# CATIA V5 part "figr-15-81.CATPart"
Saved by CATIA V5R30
Part number: Part1
Bounding box of the stored display mesh (mm): x -28.659 to 28.659, y -52 to 52, z 0 to 2
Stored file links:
  D:\PROJECTS\CATIA V56R 2020\Resources\Parts File\c15_catia_v5_6r2020_prt\figr-15-81.CATPart
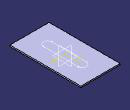
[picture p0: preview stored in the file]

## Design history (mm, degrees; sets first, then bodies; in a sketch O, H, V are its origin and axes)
SheetMetalParameters1: Thickness 2, BendRadius 4, KFactor 0.400515 {= log(min(100,max(20*SheetMetalParameters1.BendRadius,SheetMetalParameters1.Thickness)/SheetMetalParameters1.Thickness))/log(100)/2}, ReliefRadialLength 1, ReliefAxialLength 2, MinimumBendRadius 0
Body1 (main body)
  Sketch1 on xy-plane, origin (0, 0, 0), H (1, 0, 0), V (0, 1, 0)
    line L1 (28.6588, 52) -> (28.6588, -52)
    line L2 (28.6588, -52) -> (-28.6588, -52)
    line L3 (-28.6588, -52) -> (-28.6588, 52)
    line L4 (-28.6588, 52) -> (28.6588, 52)
    vertical: L1 V, L3 V
    horizontal: L2 H, L4 H
    equidistance: L1 L3 O, L2 L4 O
  Wall1: Thickness 2, Profile Sketch1, OffsetValue 0
  Sketch2 on face of Wall1, origin (0, 0, 2), H (1, 0, 0), V (0, 1, 0)
    construction line L1 (0, 25.3065) -> (0, -25.5921)
    point P1 (0, 25.3065)
    line L2 (6, 25.3065) -> (6, -25.5921)
    line L3 (-6, -25.5921) -> (-6, 25.3065)
    arc A1 centre (0, -25.5921) radius 6 from (6, -25.5921) to (-6, -25.5921) cw
    arc A2 centre (0, 25.3065) radius 6 from (-6, 25.3065) to (6, 25.3065) cw
    distance L1 L2 = 6
    coincidence: P1 V
    vertical: L1 V
    tangency: A1 L2, A2 L2, A1 L3, A2 L3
